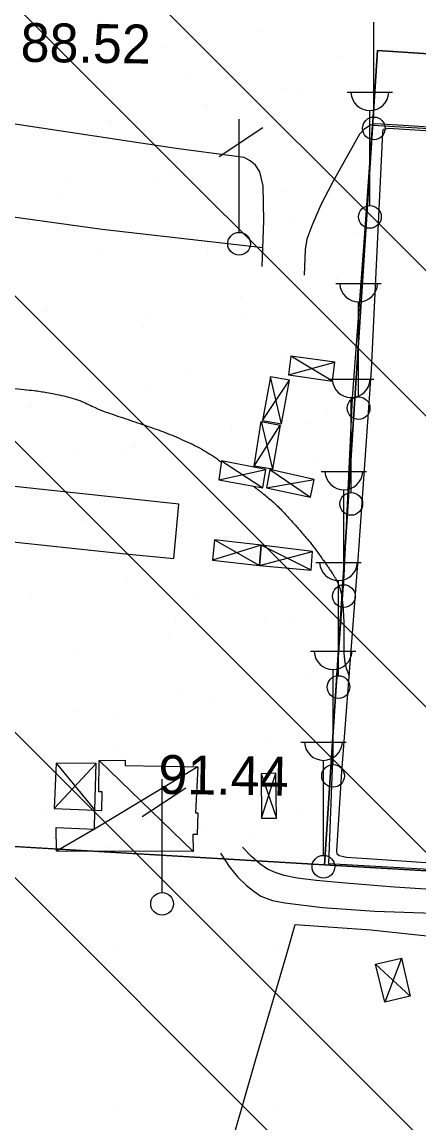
# Model space of a CAD drawing. Extents: x 417995 to 421451, y 4454518 to 4458015.
# Drawn here: x 420663.7 to 420725, y 4455397.6 to 4455567.5 of the extents above; entities that cross this region are included whole.
import ezdxf

# ---------------------------------------------------------------- set-up
doc = ezdxf.new("R2010")
doc.units = 0
for name, color, linetype in [('ADAKENARI', 7, 'Continuous'), ('B_Betonzemin', 7, 'Continuous'), ('B_Sundurma', 7, 'Continuous'), ('Egri_1m', 7, 'Continuous'), ('PL_AYA_FUAR', 7, 'Continuous'), ('PL_K_BHA', 7, 'Continuous'), ('PL_KAMU_HİZMET_ALANI', 7, 'Continuous'), ('S_Cad_Sok_Lambasi', 7, 'Continuous'), ('S_Telefon_Diregi', 7, 'Continuous'), ('Sinir_Duvar_tek_tarafa_ait', 7, 'Continuous'), ('Sinir_Ist_Duvari', 7, 'Continuous'), ('Sinir_Tel_bir_taraf', 7, 'Continuous'), ('SN_TR_SIVILASMA', 7, 'Continuous'), ('TRFAT_KHA', 7, 'Continuous'), ('TRFAT_PARKALANI', 7, 'Continuous'), ('Y_Kot_Noktasi', 7, 'Continuous'), ('Y_Yol_Kotu', 7, 'Continuous'), ('Yol_Kaldirim_kenari_bordurtasi', 7, 'Continuous'), ('Yol_Sose', 7, 'Continuous'), ('Yol_Toprak_Duz', 7, 'Continuous'), ('Yol_Toprak_Kesik', 7, 'Continuous')]:
    doc.layers.add(name, color=color, linetype=linetype)

msp = doc.modelspace()

# ---------------------------------------------------------------- linework, layer by layer
at = {"layer": 'ADAKENARI'}
for p, q in [((420718.56, 4455563.04), (420710.4, 4455437.34)), ((420884.98, 4455552.19), (420718.56, 4455563.04)), ((420549.3, 4455446.81), (420710.4, 4455437.34)), ((420710.4, 4455437.34), (420878.18, 4455427.47))]:
    msp.add_line(p, q, dxfattribs=at)
at = {"layer": 'B_Betonzemin'}
for points in [[(420687.89, 4455493.02), (420662.57, 4455495.76), (420617.14, 4455500.26), (420577.96, 4455504.2), (420566.34, 4455505.34), (420565.56, 4455496.82), (420596.64, 4455493.66), (420636.68, 4455489.9), (420679.17, 4455485.42), (420687.13, 4455484.63)], [(420687.13, 4455484.63), (420687.89, 4455493.02)]]:
    msp.add_lwpolyline(points, dxfattribs=at)
at = {"layer": 'B_Sundurma'}
for p, q in [((420704.82, 4455512.99), (420712, 4455514.91)), ((420711.63, 4455512), (420705.22, 4455515.86)), ((420703.76, 4455505.42), (420702.04, 4455512.68)), ((420700.81, 4455505.93), (420704.97, 4455512.18)), ((420700.61, 4455505.76), (420702.38, 4455498.39)), ((420699.53, 4455498.87), (420703.55, 4455505.19)), ((420694.52, 4455499.72), (420700.87, 4455495.53)), ((420694.1, 4455496.78), (420701.36, 4455498.34)), ((420701.95, 4455498.36), (420708.24, 4455494.1)), ((420701.46, 4455495.54), (420708.79, 4455496.81)), ((420693.43, 4455487.5), (420700.34, 4455483.55)), ((420700.64, 4455486.66), (420693.1, 4455484.37)), ((420700.34, 4455483.55), (420708.56, 4455485.69)), ((420708.32, 4455482.81), (420700.64, 4455486.66)), ((420690.12, 4455439.39), (420675.62, 4455453.46)), ((420668.67, 4455446.02), (420675.17, 4455452.95)), ((420668.98, 4455453.05), (420674.94, 4455445.78)), ((420690.84, 4455452.44), (420674.87, 4455442.82)), ((420700.67, 4455444.52), (420702.9, 4455451.47)), ((420700.6, 4455451.37), (420702.96, 4455444.54)), ((420674.87, 4455442.82), (420669.01, 4455439.46)), ((420722.28, 4455422.92), (420719.73, 4455416.14)), ((420718.24, 4455422.01), (420723.59, 4455417.07))]:
    msp.add_line(p, q, dxfattribs=at)
for points in [[(420704.82, 4455512.99), (420711.63, 4455512), (420712, 4455514.91), (420705.22, 4455515.86)], [(420700.81, 4455505.93), (420703.76, 4455505.42), (420704.97, 4455512.18), (420702.04, 4455512.68)], [(420699.53, 4455498.87), (420700.61, 4455505.76), (420703.55, 4455505.19), (420702.38, 4455498.39)], [(420694.52, 4455499.72), (420694.1, 4455496.78), (420700.87, 4455495.53), (420701.36, 4455498.34)], [(420701.95, 4455498.36), (420701.46, 4455495.54), (420708.24, 4455494.1), (420708.79, 4455496.81)], [(420700.64, 4455486.66), (420693.43, 4455487.5), (420693.1, 4455484.37), (420700.34, 4455483.55)], [(420700.34, 4455483.55), (420708.32, 4455482.81), (420708.56, 4455485.69), (420700.64, 4455486.66)], [(420676.04, 4455445.72), (420676.07, 4455448.58), (420675.54, 4455448.59), (420675.62, 4455453.46), (420679.64, 4455453.49), (420679.65, 4455452.64), (420690.84, 4455452.44), (420690.49, 4455445.35), (420690.83, 4455445.35), (420690.76, 4455441.99), (420690.09, 4455441.99), (420690.12, 4455439.39), (420669.01, 4455439.46), (420668.99, 4455443.08), (420674.87, 4455442.82), (420674.94, 4455445.78)], [(420668.98, 4455453.05), (420668.67, 4455446.02), (420674.94, 4455445.78), (420675.17, 4455452.95)], [(420700.6, 4455451.37), (420700.67, 4455444.52), (420702.96, 4455444.54), (420702.9, 4455451.47)], [(420718.24, 4455422.01), (420722.28, 4455422.92), (420723.59, 4455417.07), (420719.73, 4455416.14)]]:
    msp.add_lwpolyline(points, close=True, dxfattribs=at)
at = {"layer": 'Egri_1m'}
for points in [[(420592.68, 4455517.63), (420593.9, 4455517.82), (420595.12, 4455518.01), (420596.33, 4455518.2), (420597.76, 4455518.27), (420599.21, 4455518.25), (420600.66, 4455518.12), (420603.05, 4455517.82), (420605.58, 4455517.48), (420608.11, 4455517.09), (420610.54, 4455516.66), (420612.95, 4455516.22), (420615.36, 4455515.78), (420617.95, 4455515.36), (420620.6, 4455514.95), (420623.27, 4455514.6), (420628.67, 4455514.17), (420635.32, 4455513.7), (420641.97, 4455513.22), (420645.68, 4455512.9), (420647.64, 4455512.66), (420649.59, 4455512.42), (420652.04, 4455512.11), (420654.88, 4455511.74), (420657.71, 4455511.38), (420660.11, 4455511.1), (420662.07, 4455510.9), (420664.03, 4455510.71), (420665.57, 4455510.55), (420666.55, 4455510.41), (420667.53, 4455510.25), (420668.69, 4455510.03), (420670.16, 4455509.72), (420671.61, 4455509.31), (420672.93, 4455508.87), (420673.96, 4455508.4), (420674.99, 4455507.92), (420676.53, 4455507.29), (420679.6, 4455506.24), (420682.67, 4455505.19), (420685.44, 4455504.22), (420686.9, 4455503.64), (420688.34, 4455503.02), (420689.76, 4455502.37), (420691.11, 4455501.69), (420692.41, 4455500.93), (420693.61, 4455500.16), (420693.9, 4455499.94), (420694.2, 4455499.71), (420694.49, 4455499.49)], [(420699.37, 4455495.81), (420699.79, 4455495.5), (420700.2, 4455495.18), (420700.62, 4455494.87), (420701.03, 4455494.55), (420701.76, 4455493.95), (420702.52, 4455493.32), (420703.23, 4455492.63), (420703.93, 4455491.93), (420704.55, 4455491.26), (420705.16, 4455490.59), (420705.76, 4455489.92), (420706.35, 4455489.24), (420706.81, 4455488.72), (420707.22, 4455488.24), (420707.63, 4455487.77), (420708.03, 4455487.29), (420708.53, 4455486.65), (420709.07, 4455485.94), (420709.59, 4455485.22), (420710.11, 4455484.49), (420710.53, 4455483.89), (420710.89, 4455483.39), (420711.24, 4455482.88), (420711.58, 4455482.37), (420711.88, 4455481.9), (420712.14, 4455481.46), (420712.37, 4455481.01), (420712.58, 4455480.55), (420712.75, 4455480.05), (420712.9, 4455479.52), (420713.02, 4455478.99), (420713.1, 4455478.45), (420713.17, 4455477.83), (420713.24, 4455477.07), (420713.3, 4455476.31), (420713.34, 4455475.55), (420713.37, 4455474.76), (420713.37, 4455473.88), (420713.36, 4455473), (420713.36, 4455472.12), (420713.36, 4455471.28), (420713.37, 4455470.63), (420713.39, 4455469.99), (420713.45, 4455469.35), (420713.51, 4455468.71), (420713.63, 4455468.14), (420713.77, 4455467.57), (420713.98, 4455467.02), (420714.19, 4455466.48)]]:
    msp.add_spline(points, degree=3, dxfattribs=at)
at = {"layer": 'PL_AYA_FUAR'}
msp.add_lwpolyline([(420787.06, 4455778.4), (420884.04, 4455668.02), (420888.93, 4455658.72), (420890.16, 4455653.06), (420890.46, 4455645.54), (420886.58, 4455581.52), (420884.98, 4455552.19), (420718.56, 4455563.04), (420710.4, 4455437.34), (420549.3, 4455446.81)], dxfattribs=at)
at = {"layer": 'PL_K_BHA'}
msp.add_lwpolyline([(420710.4, 4455437.34), (420718.56, 4455563.04), (420884.98, 4455552.19), (420878.18, 4455427.47)], close=True, dxfattribs=at)
at = {"layer": 'PL_KAMU_HİZMET_ALANI'}
msp.add_lwpolyline([(420705.27, 4455005.33), (420707.29, 4455006.2), (420751.48, 4455032.99), (420769.07, 4455051.2), (420804.89, 4455072.7), (420840.78, 4455094.99), (420847.65, 4455100.22), (420853.39, 4455106.67), (420857.79, 4455114.1), (420861.99, 4455130.83), (420878.18, 4455427.47), (420710.4, 4455437.34), (420545.42, 4455447.04), (420544.85, 4455437.97), (420540.37, 4455429.06), (420482.57, 4455314.58), (420453.85, 4455245.63), (420452.99, 4455236.3), (420611.77, 4455234.39), (420610.24, 4455191.26), (420608.01, 4455006.36)], dxfattribs=at)
at = {"layer": 'S_Cad_Sok_Lambasi'}
for p, q in [((420718.01, 4455552.78), (420718.01, 4455567.45)), ((420713.9, 4455556.61), (420720.9, 4455556.61)), ((420717.4, 4455539.11), (420717.4, 4455553.79)), ((420712.16, 4455527.09), (420719.16, 4455527.09)), ((420715.66, 4455509.59), (420715.66, 4455524.26)), ((420711.02, 4455512.3), (420718.02, 4455512.3)), ((420714.52, 4455494.8), (420714.52, 4455509.48)), ((420709.89, 4455498.07), (420716.89, 4455498.07)), ((420713.39, 4455480.57), (420713.39, 4455495.24)), ((420709.06, 4455484.03), (420716.06, 4455484.03)), ((420712.56, 4455466.53), (420712.56, 4455481.21)), ((420708.22, 4455470.31), (420715.22, 4455470.31)), ((420711.72, 4455452.81), (420711.72, 4455467.48)), ((420706.73, 4455456.29), (420713.73, 4455456.29)), ((420710.23, 4455438.79), (420710.23, 4455453.46))]:
    msp.add_line(p, q, dxfattribs=at)
for centre in [(420718.01, 4455551.03), (420717.4, 4455537.36), (420715.66, 4455507.84), (420714.52, 4455493.05), (420713.39, 4455478.82), (420712.56, 4455464.78), (420711.72, 4455451.06), (420710.23, 4455437.04)]:
    msp.add_circle(centre, 1.75, dxfattribs=at)
for centre in [(420717.4, 4455556.71), (420715.66, 4455527.19), (420714.52, 4455512.4), (420713.39, 4455498.17), (420712.56, 4455484.14), (420711.72, 4455470.41), (420710.23, 4455456.39)]:
    msp.add_arc(centre, 2.93, 183.298, 356.9072, dxfattribs=at)
at = {"layer": 'S_Telefon_Diregi'}
for p, q in [((420697.24, 4455534.97), (420697.24, 4455552.47)), ((420694.13, 4455546.7), (420700.88, 4455551.14)), ((420685.35, 4455433.05), (420685.35, 4455450.55)), ((420682.24, 4455444.78), (420688.99, 4455449.22))]:
    msp.add_line(p, q, dxfattribs=at)
for centre in [(420697.21, 4455533.22), (420685.32, 4455431.3)]:
    msp.add_circle(centre, 1.75, dxfattribs=at)
at = {"layer": 'Sinir_Duvar_tek_tarafa_ait'}
msp.add_lwpolyline([(420711.86, 4455459.65), (420713.44, 4455482.01), (420714.73, 4455509.43), (420716.63, 4455534.8), (420717.79, 4455551.53), (420741.21, 4455550.12), (420778.05, 4455547.73)], dxfattribs=at)
at = {"layer": 'Sinir_Ist_Duvari'}
msp.add_lwpolyline([(420711.66, 4455454.86), (420711, 4455437.56), (420737.47, 4455436.02), (420761.66, 4455434.48), (420776.86, 4455433.65)], dxfattribs=at)
at = {"layer": 'Sinir_Tel_bir_taraf'}
msp.add_lwpolyline([(420674.47, 4455317.55), (420676.67, 4455325.19), (420678.96, 4455332.51), (420682.36, 4455344.86), (420685.34, 4455355.28), (420688.52, 4455366.52), (420693.32, 4455383.81), (420696.52, 4455395.83), (420699.81, 4455407.31), (420704.56, 4455423.59), (420705.85, 4455428.13), (420717.55, 4455427.28), (420734.84, 4455425.46), (420756.41, 4455423.3), (420764.21, 4455422.39), (420770.71, 4455419.91), (420776.1, 4455417), (420776.68, 4455416.51)], dxfattribs=at)
at = {"layer": 'SN_TR_SIVILASMA'}
for p, q in [((421255.58, 4454999.52), (420079.94, 4456175.16)), ((421232.89, 4454999.76), (420079.94, 4456152.71)), ((421187.51, 4455000.24), (420079.94, 4456107.81)), ((421164.82, 4455000.48), (420095.66, 4456069.64)), ((421119.44, 4455000.96), (420129.33, 4455991.06)), ((421096.75, 4455001.2), (420145.11, 4455952.83))]:
    msp.add_line(p, q, dxfattribs=at)
at = {"layer": 'TRFAT_KHA'}
for p, q in [((420677.99, 4455424.6), (420677.99, 4455424.6)), ((420702.99, 4455424.6), (420702.99, 4455424.6)), ((420677.99, 4455399.6), (420677.99, 4455399.6)), ((420702.99, 4455399.6), (420702.99, 4455399.6))]:
    msp.add_line(p, q, dxfattribs=at)
at = {"layer": 'TRFAT_PARKALANI'}
for p, q in [((420675.53, 4455567.21), (420675.53, 4455567.21)), ((420700.39, 4455566.21), (420700.39, 4455566.21)), ((420685.62, 4455563.6), (420685.62, 4455563.6)), ((420712.79, 4455561.93), (420712.79, 4455561.93)), ((420670.85, 4455561), (420670.85, 4455561)), ((420689.43, 4455559.68), (420689.43, 4455559.68)), ((420676.95, 4455557.97), (420676.95, 4455557.97)), ((420704.2, 4455557.07), (420704.2, 4455557.07)), ((420707.05, 4455557.23), (420707.05, 4455557.23)), ((420692.28, 4455554.62), (420692.28, 4455554.62)), ((420677.51, 4455552.02), (420677.51, 4455552.02)), ((420713.71, 4455548.25), (420713.71, 4455548.25)), ((420686.83, 4455544.91), (420686.83, 4455544.91)), ((420698.94, 4455545.64), (420698.94, 4455545.64)), ((420671.19, 4455542.59), (420671.19, 4455542.59)), ((420684.17, 4455543.04), (420684.17, 4455543.04)), ((420703.9, 4455541.42), (420703.9, 4455541.42)), ((420669.4, 4455540.44), (420669.4, 4455540.44)), ((420668.06, 4455537.46), (420668.06, 4455537.46)), ((420700.73, 4455537.38), (420700.73, 4455537.38)), ((420705.6, 4455536.66), (420705.6, 4455536.66)), ((420715.5, 4455534.77), (420715.5, 4455534.77)), ((420690.83, 4455534.06), (420690.83, 4455534.06)), ((420676.06, 4455531.46), (420676.06, 4455531.46)), ((420692.4, 4455531.78), (420692.4, 4455531.78)), ((420712.26, 4455527.69), (420712.26, 4455527.69)), ((420697.49, 4455525.08), (420697.49, 4455525.08)), ((420667.71, 4455522.89), (420667.71, 4455522.89)), ((420682.72, 4455522.48), (420682.72, 4455522.48)), ((420698.13, 4455522.61), (420698.13, 4455522.61)), ((420667.95, 4455519.87), (420667.95, 4455519.87)), ((420682.49, 4455520.29), (420682.49, 4455520.29)), ((420704.15, 4455516.1), (420704.15, 4455516.1)), ((420712.03, 4455515.08), (420712.03, 4455515.08)), ((420689.38, 4455513.5), (420689.38, 4455513.5)), ((420674.61, 4455510.89), (420674.61, 4455510.89)), ((420683.51, 4455511.26), (420683.51, 4455511.26)), ((420665.11, 4455508.12), (420665.11, 4455508.12)), ((420710.81, 4455507.12), (420710.81, 4455507.12)), ((420696.04, 4455504.52), (420696.04, 4455504.52)), ((420707.86, 4455505.58), (420707.86, 4455505.58)), ((420672.02, 4455501.62), (420672.02, 4455501.62)), ((420681.27, 4455501.91), (420681.27, 4455501.91)), ((420666.5, 4455499.31), (420666.5, 4455499.31)), ((420679.01, 4455500.59), (420679.01, 4455500.59)), ((420709.42, 4455500.31), (420709.42, 4455500.31)), ((420693.78, 4455497.99), (420693.78, 4455497.99)), ((420702.7, 4455495.54), (420702.7, 4455495.54)), ((420687.93, 4455492.93), (420687.93, 4455492.93)), ((420673.16, 4455490.33), (420673.16, 4455490.33)), ((420676.41, 4455485.82), (420676.41, 4455485.82)), ((420709.36, 4455486.56), (420709.36, 4455486.56)), ((420694.59, 4455483.95), (420694.59, 4455483.95)), ((420698.97, 4455485.07), (420698.97, 4455485.07)), ((420679.82, 4455481.35), (420679.82, 4455481.35)), ((420665.04, 4455478.74), (420665.04, 4455478.74)), ((420690.31, 4455478.29), (420690.31, 4455478.29)), ((420687.47, 4455475.42), (420687.47, 4455475.42)), ((420705.08, 4455475.69), (420705.08, 4455475.69)), ((420701.25, 4455474.97), (420701.25, 4455474.97)), ((420686.48, 4455472.37), (420686.48, 4455472.37)), ((420671.71, 4455469.76), (420671.71, 4455469.76)), ((420707.91, 4455465.99), (420707.91, 4455465.99)), ((420687.71, 4455463.52), (420687.71, 4455463.52)), ((420693.14, 4455463.39), (420693.14, 4455463.39)), ((420672.07, 4455461.2), (420672.07, 4455461.2)), ((420678.37, 4455460.78), (420678.37, 4455460.78)), ((420678.58, 4455454.91), (420678.58, 4455454.91)), ((420701.61, 4455455.99), (420701.61, 4455455.99)), ((420699.8, 4455454.41), (420699.8, 4455454.41)), ((420685.03, 4455451.8), (420685.03, 4455451.8)), ((420670.25, 4455449.2), (420670.25, 4455449.2)), ((420702.93, 4455449.23), (420702.93, 4455449.23)), ((420667.09, 4455445.27), (420667.09, 4455445.27)), ((420706.46, 4455445.43), (420706.46, 4455445.43)), ((420668.59, 4455441.5), (420668.59, 4455441.5)), ((420691.69, 4455442.82), (420691.69, 4455442.82)), ((420699.01, 4455441.22), (420699.01, 4455441.22)), ((420676.91, 4455440.22), (420676.91, 4455440.22))]:
    msp.add_line(p, q, dxfattribs=at)
at = {"layer": 'Yol_Kaldirim_kenari_bordurtasi'}
msp.add_lwpolyline([(420700.89, 4455532.57), (420676.07, 4455535.43), (420635.23, 4455541.07), (420601.69, 4455545.21), (420575.38, 4455548.03), (420576.18, 4455561.67)], dxfattribs=at)
at = {"layer": 'Yol_Sose'}
for points in [[(420700.79, 4455529.7), (420701.04, 4455536.78), (420700.91, 4455542.18), (420700.42, 4455544.3), (420699.73, 4455545.34), (420698.94, 4455546.03), (420698.01, 4455546.51), (420696.81, 4455546.71), (420687.48, 4455547.93), (420642.14, 4455554.75), (420579.64, 4455561.39), (420566.63, 4455562.44), (420558.05, 4455562.48), (420556.15, 4455562.16), (420554.24, 4455561.16), (420552.92, 4455559.95), (420551.6, 4455557.85), (420550.39, 4455554.27), (420548.7, 4455543.4)], [(420778.06, 4455548.01), (420754.81, 4455549.39), (420721.73, 4455551.54), (420718.24, 4455551.72), (420717.51, 4455551.55), (420716.49, 4455550.87), (420715.82, 4455550.16), (420711.68, 4455542.79), (420709.84, 4455539.2), (420708.42, 4455535.98), (420707.65, 4455533.91), (420707.42, 4455532.32), (420707.25, 4455528.38)], [(420776.87, 4455434.58), (420772.16, 4455434.88), (420754.95, 4455436.1), (420726.8, 4455437.61), (420716.97, 4455438.24), (420713.79, 4455438.48), (420713.1, 4455438.61), (420712.64, 4455438.71), (420712.36, 4455438.95), (420712.28, 4455439.47), (420713.05, 4455451.68), (420715.57, 4455484.47), (420717.66, 4455513.73), (420719.28, 4455548.22), (420719.41, 4455550.54), (420719.52, 4455550.91), (420720.27, 4455551.08), (420736.62, 4455550.05), (420778.05, 4455547.36)]]:
    msp.add_lwpolyline(points, dxfattribs=at)
at = {"layer": 'Yol_Toprak_Duz'}
msp.add_lwpolyline([(420694.32, 4455439.15), (420695.66, 4455437.07), (420697.01, 4455435.44), (420698.36, 4455434.16), (420699.51, 4455433.28), (420700.58, 4455432.51), (420701.41, 4455432.17), (420702.38, 4455431.83), (420704.26, 4455431.48), (420710.1, 4455430.73), (420718.17, 4455430.2), (420731.64, 4455429.72), (420739.57, 4455429.5), (420748.95, 4455428.47), (420756.78, 4455427.74), (420764.72, 4455427.22), (420775.57, 4455426.94), (420776.79, 4455426.9)], dxfattribs=at)
at = {"layer": 'Yol_Toprak_Kesik'}
msp.add_lwpolyline([(420776.83, 4455431.45), (420766.35, 4455431.76), (420758.01, 4455431.89), (420751.18, 4455432.25), (420745.04, 4455432.47), (420738.46, 4455433), (420732.42, 4455433.18), (420721.21, 4455433.86), (420713.64, 4455434.49), (420709.1, 4455434.89), (420706.15, 4455435.26), (420704.18, 4455435.66), (420702.77, 4455436.15), (420701.59, 4455436.66), (420700.42, 4455437.47), (420699.13, 4455438.63), (420697.76, 4455440.07)], dxfattribs=at)

# ---------------------------------------------------------------- texts
at = {"layer": 'Y_Kot_Noktasi'}
msp.add_text('91.44', height=6, rotation=359.1542, dxfattribs=at).set_placement((420684.73, 4455448.3))
at = {"layer": 'Y_Yol_Kotu'}
msp.add_text('88.52', height=6, rotation=359.1542, dxfattribs=at).set_placement((420663.46, 4455561.32))

doc.saveas('drawing.dxf')
